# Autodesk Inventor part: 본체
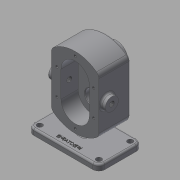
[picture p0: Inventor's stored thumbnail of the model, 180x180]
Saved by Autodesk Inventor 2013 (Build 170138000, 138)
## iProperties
Created: 2019-03
Part Number: 본체
Material: 일반
Document SubType Name: Modeling
Designer: Administrator
Density: 1 g/cm^3
Author: Administrator
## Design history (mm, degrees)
sketch "스케치1"
  geometry: L1 (-40, 60)-(40, 60); L2 (40, 60)-(40, -60); L3 (40, -60)-(-40, -60); L4 (-40, -60)-(-40, 60); L5 (-40, 60)-(40, -60); L6 (40, 60)-(-40, -60); A1 r 60 centre (0, 0) between (40, 44.721) and (-40, 44.721); A2 r 60 centre (0, 0) between (-40, -44.721) and (40, -44.721); 3 further points
  constraints: 12 end point, 6 point on circle, 4 midpoint, 4 point on line, 2 centre point, 2 parallel, 1 horizontal, 1 perpendicular
  dimensions: "d0" = 80 distance of L2.end L3.end; "d1" = 120 distance of L1.end L2.end; "d2" = 60 radius of A1; "d3" = 60 radius of A2
extrude "돌출1" new body sketch "스케치1" distance "d4" = 53; taper "d5" = 0 deg
sketch "스케치2"
  geometry: L1 (-24, -22)-(24, -22); L2 (24, -22)-(24, 22); L3 (24, 22)-(-24, 22); L4 (-24, 22)-(-24, -22); L5 (-24, -22)-(24, 22); L6 (24, -22)-(-24, 22); 3 further points
  constraints: 12 end point, 4 midpoint, 2 horizontal alignment, 2 parallel, 1 horizontal, 1 perpendicular, 4 other
  dimensions: "d6" = 48 distance of L3.end L2.end; "d7" = 44 distance of L2.end L1.end
extrude "돌출2" cut sketch "스케치2" distance "d8" = 29; taper "d9" = 0 deg
sketch "스케치3"
  geometry: C1 r 12.5 at (0, -22); C2 r 12.5 at (0, 22); A1 r 24 centre (0, 22) between (24, 22) and (-24, 22) reference; A2 r 24 centre (0, -22) between (-24, -22) and (24, -22) reference; 1 further point
  constraints: 2 centre point, 2 coincident
  dimensions: "d10" = 25 diameter of C1; "d11" = 25 diameter of C2
extrude "돌출3" cut sketch "스케치3" distance "d12" = 15; taper "d13" = 0 deg
sketch "스케치5"
  geometry: C1 r 19 at (0, 22); 1 further point
  constraints: 1 centre point
  dimensions: "d17" = 38 diameter of C1; "d18" = 22 distance of C1.centre point (0, 0)
extrude "돌출5" join sketch "스케치5" distance "d19" = 17; taper "d20" = 0 deg
sketch "스케치4"
  geometry: C1 r 12.5 at (0, 0) reference; C2 r 8.5 at (0, 0); 1 further point
  constraints: 1 centre point, 1 coincident
  dimensions: "d14" = 17 diameter of C2
extrude "돌출4" cut sketch "스케치4" stored distance "d15" = 15; taper "d16" = 0 deg
sketch "스케치8"
  geometry: L1 (3, -70)-(41, -70) reference; L2 (41, -53)-(3, -53) reference; L3 (13.5, -44)-(13.5, -70) reference; L4 (22, -53)-(22, -70); L5 (30.5, -44)-(30.5, -70) reference; L6 (22, -62.7)-(36, -62.7); L7 (36, -62.7)-(36, -69.3); L8 (36, -69.3)-(36.404, -70); 1 further point
  constraints: 8 end point, 2 midpoint, 2 perpendicular, 2 point on line
  dimensions: "d30" = 28 diameter of L7 L4; "d31" = 7.3 distance from line of L8.end L6; "d32" = 0.7 vertical distance of L8.end L7.end; "d33" = 30 deg angle of L8 L7
revolve "회전1" sketch "스케치8" stored, may be unused: angle "d34" = 90 deg
sketch "스케치9"
  geometry: L1 (0, 0)-(0, 89.443) reference; C1 r 11 at (14, 44.721); 2 further points
  constraints: 1 centre point, 1 horizontal alignment, 1 midpoint
  dimensions: "d35" = 22 diameter of C1; "d36" = 14 distance from line of C1.centre L1
extrude "돌출7" join sketch "스케치9" distance "d37" = 8; taper "d38" = 0 deg
sketch "스케치10"
  geometry: C1 r 11 at (0, 0) reference; 2 further points
  constraints: 1 coincident
hole "구멍1" sketch "스케치10" at (0, 0) diameter "d39" = 8.376; stored, may be unused: countersink angle "d43" = 90 deg, drill point angle "d45" = 118 deg; dims "d40" = 6, "d41" = 4, "d42" = 2, "d44" = 8
node "작업 평면1"
node "작업 평면2"
sketch "스케치13"
  geometry: L1 (-40, -53)-(40, -53) reference; L2 (60, -53)-(-60, -53); L3 (-60, -53)-(-60, 20); L4 (-60, 20)-(60, 20); L5 (60, 20)-(60, -53); 2 further points
  constraints: 8 end point, 2 midpoint, 2 parallel, 1 horizontal, 1 perpendicular
  dimensions: "d56" = 73 distance of L4.end L2.start; "d58" = 120 distance of L3.end L4.end
extrude "돌출9" join sketch "스케치13" distance "d59" = 10; taper "d60" = 0 deg
sketch "스케치14"
  geometry: L1 (60, 53)-(-60, 53) reference; L2 (-6, 53)-(6, 53); L3 (6, 53)-(6, 10); L4 (6, 10)-(-6, 10); L5 (-6, 10)-(-6, 53); 2 further points
  constraints: 8 end point, 2 parallel, 1 horizontal, 1 midpoint, 1 perpendicular, 1 point on line, 1 vertical alignment
  dimensions: "d61" = 43 distance of L4.end L2.start; "d63" = 12 distance of L3.end L4.end
extrude "돌출10" join sketch "스케치14" stored distance "d64" = 10; taper "d65" = 0 deg
fillet "모깎기1" dims "d66" = 10
fillet "모깎기2" dims "d67" = 10
fillet "모깎기4" dims "d69" = 3
fillet "모깎기5" dims "d70" = 3
fillet "모깎기6" dims "d71" = 3
fillet "모깎기7" dims "d72" = 3
sketch "스케치15"
  geometry: A1 r 7 centre (-50, 43) between (-50, 50) and (-57, 43) reference; A2 r 7 centre (-50, -10) between (-57, -10) and (-50, -17) reference; A3 r 7 centre (50, -10) between (50, -17) and (57, -10) reference; A4 r 7 centre (50, 43) between (57, 43) and (50, 50) reference; 5 further points
  constraints: 4 coincident
hole "구멍2" sketch "스케치15" at (-50, 43), (-50, -10), (50, -10), (50, 43) diameter "d73" = 9; stored, may be unused: countersink angle "d77" = 90 deg, drill point angle "d79" = 118 deg; dims "d74" = 6, "d75" = 4, "d76" = 2, "d78" = 8
fillet "모깎기8" dims "d80" = 0.5
chamfer "모따기1" distance "d81" = 1; stored, may be unused: second distance "d82" = 2, angle "d83" = 45 deg
fillet "모깎기9" dims "d84" = 3
fillet "모깎기10" dims "d85" = 3
sketch "스케치16"
  geometry: L1 (24, 22)-(24, -22) reference; L2 (0, 22)-(0, 53); L3 (0, 22)-(31, 22); L4 (0, 22)-(-31, 22); A1 r 24 centre (0, 22) between (24, 22) and (-24, 22) reference; 3 further points
  constraints: 6 end point, 3 coincident, 1 collinear, 1 parallel, 1 perpendicular
  dimensions: "d86" = 31 distance of L2.start L2.end; "d87" = 31 distance of L2.start L3.end; "d88" = 31 distance of L2.start L4.end
hole "구멍3" sketch "스케치16" at (0, 53), (31, 22), (-31, 22) diameter "d89" = 4.134; stored, may be unused: countersink angle "d93" = 90 deg, drill point angle "d95" = 118 deg; dims "d90" = 10, "d91" = 4, "d92" = 2, "d94" = 12
sketch "스케치17"
  geometry: L1 (-50, -20)-(50, -20) reference; L2 (-60, 43)-(-60, -10) reference; 2 further points
  constraints: 1 other
  dimensions: "d96" = 10 distance from line of L1 point (0, -10); "d97" = 60 distance from line of L2 point (0, -10)
feature "엠보싱1" sketch "스케치17" dims "d0" = 80, "d1" = 120, "d2" = 60, "d3" = 60, "d98" = 0.5, "d99" = 0
node "솔리드1"
mirror "대칭1"
mirror "대칭2"
other parameters: "d46" = -78, "d55" = -78
